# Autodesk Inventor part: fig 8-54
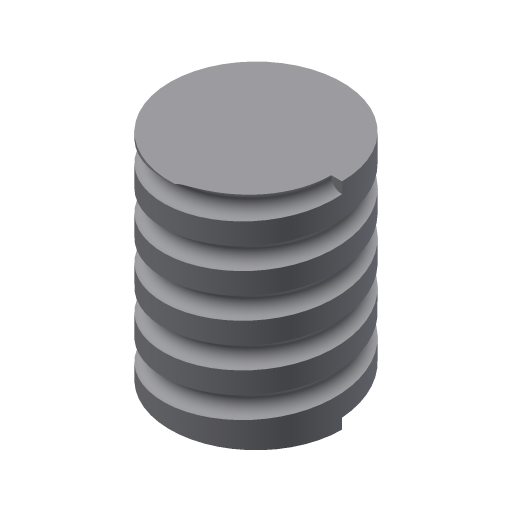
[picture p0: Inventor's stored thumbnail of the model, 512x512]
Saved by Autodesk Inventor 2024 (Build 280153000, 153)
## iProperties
Shininess: 77.0
Length Units: 11269
Angle Units: 11279
Time Units: 11290
Mass Units: 11283
Length Display Precision: 3
Angle Display Precision: 2
Created: 2002-01
Part Number: fig 8-54
Document SubType Name: Modeling
Designer: CADSoft
Density: 1 g/cm^3
Material: Generic
Appearance: Default
Density: 0.0
Volumn: 0.0
Area: 0.0
PropertySet Name: Model Information
Control State: 0
Master: False
Checked Out: False
Author: CADSoft
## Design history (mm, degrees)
sketch "Sketch4"
  geometry: C1 r 20 at (0, 0)
  constraints: 1 centre point
  dimensions: "d44" = 40 diameter of C1
sketch "Sketch2"
  geometry: C1 r 2.5 at (-20, -0.092); 1 further point
  constraints: 1 centre point, 1 other
  dimensions: "d0" = 5 diameter of C1; "d43" = 20 horizontal distance of C1.centre point (0, 0)
extrude "Extrusion2" join sketch "Sketch4" distance "d45" = 50; taper "d46" = 0 deg
coil "Coil6" pitch "d47" = 10; turns "d49" = 5; dims "d48" = 10, "d50" = 0, angle "d51" = 90 deg, angle "d52" = 90 deg, "d53" = 0, "d54" = 0
body "Solid1"
